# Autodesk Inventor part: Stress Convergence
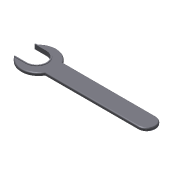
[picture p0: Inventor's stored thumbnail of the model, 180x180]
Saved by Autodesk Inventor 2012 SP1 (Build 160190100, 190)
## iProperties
Created: 2007-04
Part Number: Stress Convergence
Document SubType Name: Modeling
Designer: Junior
Material: Steel, High Strength Low Alloy
Mass: 43.5643 g
Surface Area: 45.3977 cm^2
Volume: 5.55667 cm^3
Density: 7.84 g/cm^3
Author: Junior
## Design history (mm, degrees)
node "Pracovní rovina1"
node "Pracovní rovina2"
feature "Split1 - For FEA"
body "Solid1"
sketch "Náčrt1"
  geometry: L1 (-13.851, 15.039)-(-2.622, 15.039); L2 (-2.622, -2.961)-(-13.851, -2.961); L3 (13.234, 14.039)-(97.378, 14.039); L4 (97.378, -1.961)-(13.234, -1.961); A1 r 9 centre (-2.622, 6.039) between (-2.622, -2.961) and (-2.622, 15.039); A2 r 16 centre (-0.622, 6.039) between (-13.851, -2.961) and (13.234, -1.961); A3 r 16 centre (-0.622, 6.039) between (13.234, 14.039) and (-13.851, 15.039); A4 r 8 centre (97.378, 6.039) between (97.378, -1.961) and (97.378, 14.039)
  constraints: 8 end point, 8 point on circle, 4 centre point, 4 tangent, 3 parallel, 1 horizontal, 1 horizontal alignment
  dimensions: "d0" = 16 distance between parallel lines of L4 L3; "d1" = 18 distance between parallel lines of L2 L1; "d2" = 2 distance of A2.centre A1.centre; "d3" = 8 distance from line of A2.centre L3; "d16" = 16 radius of A3; "d17" = 16 radius of A2; "d18" = 100 distance of A4.centre A1.centre
extrude "Extrusion1" new body sketch "Náčrt1" distance "d6" = 3; taper "d7" = 0 deg
sketch "Náčrt2"
  geometry: L1 (-2.622, 15.039)-(-13.851, 15.039) reference; L2 (-13.851, -2.961)-(-2.622, -2.961) reference; L3 (-2.622, 16.039)-(-13.112, 16.039); L4 (-13.112, -3.961)-(-2.622, -3.961); A1 r 16 centre (-0.622, 6.039) between (13.234, 14.039) and (-13.851, 15.039) reference; A2 r 9 centre (-2.622, 6.039) between (-2.622, -2.961) and (-2.622, 15.039) reference; A3 r 16 centre (-0.622, 6.039) between (-13.851, -2.961) and (13.234, -1.961) reference; A4 r 8 centre (97.378, 6.039) between (97.378, -1.961) and (97.378, 14.039) reference; A5 r 3.737 centre (97.378, 6.039) between (97.378, 2.302) and (97.378, 9.775); A6 r 10 centre (-2.622, 6.039) between (-2.622, -3.961) and (-2.622, 16.039)
  constraints: 6 point on circle, 4 end point, 2 centre point, 2 tangent, 1 parallel
  dimensions: "d8" = 1 distance between parallel lines of L2 L4
extrude "Extrusion2" join sketch "Náčrt2" distance "d9" = 0.5; taper "d10" = 0 deg
mirror "Mirror1"
fillet "Fillet1" dims "d12" = 10
chamfer "Chamfer1" distance "d13" = 0.5; stored, may be unused: second distance "d14" = 2, angle "d15" = 45 deg
fillet "Fillet2" dims "d19" = 0.2
fillet "Fillet3" dims "d20" = 1
fillet "Fillet4" dims "d21" = 1
other parameters: "d4" = 9, "d11" = -1.5, "d23" = 1000000
